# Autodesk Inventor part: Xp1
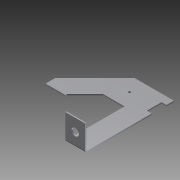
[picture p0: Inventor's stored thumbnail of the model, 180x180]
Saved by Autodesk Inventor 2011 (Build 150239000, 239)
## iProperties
Created: 2014-11
Part Number: Xp1
Document SubType Name: Modeling
Designer: Evgeny
Density: 1 g/cm^3
Author: Evgeny
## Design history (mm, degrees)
sketch "Эскиз1"
  geometry: L1 (0, 0)-(-8, 0); L2 (-8, 0)-(-8, 24); L3 (-8, 24)-(-16.686, 24); L4 (-16.686, 24)-(-24, 16.686); L5 (-24, 16.686)-(-24, 16); L6 (-24, 16)-(-32, 16); L7 (-32, 16)-(-32, 20); L8 (-32, 20)-(-16, 36); L9 (-16, 36)-(0, 36); L10 (0, 33)-(-2, 33); L11 (-2, 33)-(-2, 27); L12 (-2, 27)-(0, 27); L13 (0, 36)-(0, 33); L14 (0, 27)-(0, 0)
  constraints: 28 end point, 8 parallel, 6 perpendicular, 1 collinear, 1 horizontal
  dimensions: "d0" = 36 distance between parallel lines of L9 L1; "d2" = 12 distance between parallel lines of L3 L9; "d3" = 8 distance between parallel lines of L8 L4; "d4" = 16 distance of L8.end L9.end; "d5" = 135 deg angle of L9 L8; "d6" = 8 distance between parallel lines of L7 L5; "d7" = 16 distance between parallel lines of L2 L5; "d8" = 16 distance between parallel lines of L6 L1; "d31" = 6 distance between parallel lines of L12 L10; "d32" = 3 distance between parallel lines of L9 L10; "d33" = 2 distance between parallel lines of L11 L13; "d34" = 8 distance between parallel lines of L2 L14
extrude "Выдавливание1" new body sketch "Эскиз1" distance "d9" = 0.5; taper "d10" = 0 deg
sketch "Эскиз2"
  geometry: L1 (0, 36)-(0, 0) reference; L2 (-8, 0)-(0, 0); L3 (0, 0)-(0, 0.5); L4 (0, 0.5)-(-8, 0.5); L5 (-8, 0.5)-(-8, 0)
  constraints: 8 end point, 2 parallel, 1 horizontal, 1 perpendicular, 1 point on line
  dimensions: "d12" = 0.5 distance between parallel lines of L4 L2
extrude "Выдавливание2" join sketch "Эскиз2" distance "d13" = 10; taper "d14" = 0 deg
fillet "Сопряжение1" dims "d15" = 0.5
fillet "Сопряжение2" dims "d16" = 1
sketch "Эскиз3"
  geometry: L1 (8, -9.5)-(8, 0) reference; L2 (8, 0)-(0, 0) reference; C1 r 1.5 at (4, -5); 1 further point
  constraints: 1 centre point
  dimensions: "d17" = 3 diameter of C1; "d18" = 5 distance from line of C1.centre L2; "d19" = 4 distance from line of L1 C1.centre
extrude "Выдавливание3" cut sketch "Эскиз3" distance "d20" = 1; taper "d21" = 0 deg
hole "Отверстие1" diameter "d24" = 1; stored, may be unused: countersink angle "d28" = 90 deg, drill point angle "d30" = 118 deg; dims "d22" = 6, "d23" = 12, "d25" = 6, "d26" = 4, "d27" = 2, "d29" = 1
node "Твердое тело1"
other parameters: "d1" = 8, "d11" = 32 (derived)
